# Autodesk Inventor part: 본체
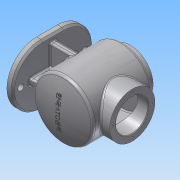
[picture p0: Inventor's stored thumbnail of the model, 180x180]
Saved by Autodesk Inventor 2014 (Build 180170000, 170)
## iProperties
Created: 2016-04
Part Number: 본체
Material: 알루미늄 6061
Document SubType Name: Modeling
Designer: 601-
Density: 2.71 g/cm^3
Appearance: 알루미늄 - 평지
Mass: 1195.29 g
Surface Area: 1196.97 cm^2
Volume: 441.067 cm^3
Author: 601-
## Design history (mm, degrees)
sketch "스케치2"
  geometry: L1 (-17.5, 0)-(17.5, 0); L2 (-17.5, -50)-(17.5, -50); L3 (17.5, 50)-(-17.5, 50); L4 (-67.5, 0)-(67.5, 0); L5 (0, 50)-(0, -50); A1 r 50 centre (-17.5, 0) between (-17.5, 50) and (-17.5, -50); A2 r 50 centre (17.5, 0) between (17.5, -50) and (17.5, 50); 1 further point
  constraints: 12 end point, 6 point on circle, 4 tangent, 3 midpoint, 2 centre point, 1 horizontal, 1 parallel
  dimensions: "d0" = 135 distance of L4.end L4.start; "d1" = 100 distance of L5.end L5.start
extrude "돌출1" new body sketch "스케치2" distance "d2" = 10; taper "d3" = 0 deg
sketch "스케치3"
  geometry: L1 (0, -67.5)-(0, 67.5); C1 r 5 at (0, -54); C2 r 5 at (0, 54); A1 r 50 centre (0, 17.5) between (50, 17.5) and (-50, 17.5) reference; A2 r 50 centre (0, -17.5) between (-50, -17.5) and (50, -17.5) reference; 1 further point
  constraints: 2 centre point, 2 end point, 2 point on circle, 2 point on line, 1 equal radius
  dimensions: "d4" = 10 diameter of C1; "d5" = 108 distance of C2.centre C1.centre; "d6" = 54 distance of point (0, 0) C1.centre
extrude "돌출2" cut sketch "스케치3" stored distance "d7" = 10; taper "d8" = 0 deg
sketch "스케치5"
  geometry: L1 (0, 0)-(79, 0); L2 (0, -17.5)-(0, 17.5) reference; L3 (79, 61)-(79, -61); L4 (79, 61)-(117, 61); L5 (117, 61)-(117, 49); L6 (117, 49)-(79, 49); L7 (79, 49)-(79, 61); L8 (79, 49)-(129, 49); L9 (129, 49)-(129, -51); L10 (79, -49)-(79, 49); L11 (79, -49)-(79, -61); L12 (79, -49)-(79, -61); L13 (79, -51)-(79, -61); L14 (79, -51)-(129, -51); L15 (79, 49)-(129, 49); L16 (129, 49)-(129, -51); L17 (129, -51)-(79, -51); L18 (79, -51)-(79, 49); L19 (129, -51)-(79, -51); L20 (0, 67.5)-(10, 67.5) reference; L21 (0, -67.5)-(10, -67.5) reference; A1 r 120 centre (81.003, 58.983) between (79, -61) and (129, -51)
  constraints: 36 end point, 6 parallel, 5 perpendicular, 4 collinear, 3 horizontal, 2 midpoint, 2 point on circle, 1 centre point, 1 point on line
  dimensions: "d19" = 79 distance of L1.end L1.start; "d21" = 12 distance of L4.end L5.end; "d22" = 100 diameter of L9 L3; "d23" = 76 diameter of L5 L3; "d25" = 122 distance from line of L12.end L4; "d28" = 120 radius of A1; "d41" = 61 distance from line of L1.end L4
revolve "회전1" stored, may be unused: angle "d29" = 90 deg
revolve "회전2" stored, may be unused: angle "d30" = 90 deg
sketch "스케치8"
  geometry: L1 (-40, 5)-(40, 5); L2 (40, 5)-(40, -5); L3 (40, -5)-(-40, -5); L4 (-40, -5)-(-40, 5); L5 (-40, 5)-(40, -5); L6 (40, 5)-(-40, -5); 1 further point
  constraints: 12 end point, 2 midpoint, 2 parallel, 1 horizontal, 1 perpendicular
  dimensions: "d37" = 80 distance of L1.start L1.end; "d38" = 10 distance of L1.end L2.end
extrude "돌출4" join sketch "스케치8" stored distance "d39" = 10; taper "d40" = 0 deg
sketch "스케치9"
  geometry: L1 (10, 67.5)-(10, 59) reference; L2 (10, 59)-(0, 59) reference; L3 (0, 59)-(0, 67.5) reference; L4 (0, 67.5)-(10, 67.5) reference; L5 (10, -67.5)-(0, -67.5) reference; L6 (0, -67.5)-(0, -59) reference; L7 (0, -59)-(10, -59) reference; L8 (10, -59)-(10, -67.5) reference; L9 (41, 61)-(117, 61) reference; L10 (117, 61)-(117, 49) reference; L11 (117, 49)-(129, 49) reference; L12 (129, 49)-(129, -51) reference; L13 (29, -51)-(29, -5) reference; L14 (10, -5)-(10, -49) reference; L15 (10, -49)-(0, -49) reference; L16 (0, -49)-(0, 49) reference; L17 (0, 49)-(10, 49) reference; L18 (10, 49)-(10, 5) reference; L19 (29, 5)-(29, 49) reference; L20 (29, 49)-(41, 49) reference; L21 (41, 49)-(41, 61) reference; L22 (41, 61)-(117, 61) reference; L23 (79, 46)-(79, -58); L24 (32, -49.018)-(32, 46); L25 (32, 46)-(79, 46); L26 (29, -5)-(10, -5) reference; L27 (10, 5)-(29, 5) reference; A1 r 120 centre (81.003, 58.983) between (79, -61) and (129, -51) reference; A2 r 120 centre (76.997, 58.983) between (29, -51) and (79, -61) reference; A3 r 117 centre (76.997, 58.983) between (32, -49.018) and (79, -58); 1 further point
  constraints: 6 end point, 2 point on circle, 2 symmetric about line, 1 centre point, 1 perpendicular
  dimensions: "d132" = 3 distance between parallel lines of L13 L24
revolve "회전3" sketch "스케치9" stored, may be unused: angle "d46" = 90 deg
sketch "스케치10"
  geometry: C1 r 38 at (0, 0) reference; C2 r 27 at (0, 0); 1 further point
  constraints: 1 centre point, 1 coincident
  dimensions: "d47" = 54 diameter of C2
extrude "돌출5" cut sketch "스케치10" distance "d48" = 15; taper "d49" = 0 deg
sketch "스케치11" dims "d50" = 65
  geometry: C1 r 38 at (0, 0) reference; 3 further points
  constraints: 1 coincident, 1 horizontal alignment, 2 other
hole "구멍1" sketch "스케치11" at (32.5, 0) diameter "d51" = 3.242; stored, may be unused: countersink angle "d55" = 90 deg, drill point angle "d57" = 118 deg; dims "d52" = 8, "d53" = 4, "d54" = 2, "d56" = 10
node "작업 평면2"
sketch "스케치12"
  geometry: L1 (49, 50)-(49, -50) reference; C1 r 38 at (-1, 0); 1 further point
  constraints: 1 centre point
  dimensions: "d102" = 50 distance from line of L1 C1.centre; "d103" = 76 diameter of C1
extrude "돌출6" join sketch "스케치12" stored distance "d63" = 10; taper "d64" = 0 deg
chamfer "모따기1" distance "d89" = 3; stored, may be unused: second distance "d90" = 2, angle "d91" = 45 deg
fillet "모깎기4" dims "d92" = 3
fillet "모깎기6" dims "d94" = 5, "d95" = 2
chamfer "모따기2" distance "d96" = 1; stored, may be unused: second distance "d97" = 2, angle "d98" = 45 deg
sketch "스케치16"
  geometry: L1 (107, 61)-(51, 61) reference; L2 (79, 61)-(79, -71.856); 1 further point
  constraints: 2 end point, 1 midpoint, 1 perpendicular
fillet "모깎기7" dims "d101" = 3
sketch "스케치18"
  geometry: C1 r 38 at (0, 0) reference; C2 r 27 at (0, 0); 1 further point
  constraints: 1 centre point, 1 coincident
  dimensions: "d104" = 54 diameter of C2
extrude "돌출8" cut sketch "스케치18" stored distance "d105" = 10; taper "d106" = 0 deg
sketch "스케치19" dims "d107" = 65
  geometry: C1 r 38 at (0, 0) reference; 3 further points
  constraints: 1 coincident, 1 vertical alignment, 2 other
hole "구멍4" sketch "스케치19" at (0, 32.5) diameter "d108" = 3.242; stored, may be unused: countersink angle "d112" = 90 deg, drill point angle "d114" = 118 deg; dims "d109" = 8, "d110" = 4, "d111" = 2, "d113" = 10
fillet "모깎기8" dims "d118" = 3
chamfer "모따기3" distance "d119" = 1; stored, may be unused: second distance "d120" = 2, angle "d121" = 45 deg
sketch "스케치20"
  geometry: L1 (52, 60)-(106, 60) reference; L2 (79, 60)-(79, -71.197); 1 further point
  constraints: 2 end point, 1 midpoint, 1 perpendicular
node "작업 평면5"
sketch "스케치21"
  geometry: C1 r 50 at (0, 0) reference; 2 further points
  constraints: 1 coincident, 1 other
feature "엠보싱2" sketch "스케치21" dims "d0" = 135, "d1" = 100, "d7" = 10, "d8" = 0, "d122" = 0.5, "d123" = 0
sketch "스케치22"
  geometry: L1 (10, 64.5)-(10, 17.5) reference; L2 (10, -17.5)-(10, -64.5) reference; L3 (10, 40)-(33.936, 35.779); L4 (33.936, 35.779)-(33.936, -35.779); L5 (33.936, -35.779)-(10, -40); L6 (10, 40)-(10, -40); L7 (0, 0)-(62.313, 0); L8 (49, -2)-(10, -2) reference; 2 further points
  constraints: 10 end point, 2 parallel, 2 point on line, 1 collinear
  dimensions: "d124" = 40 distance from line of L7 L3.start; "d125" = 40 distance from line of L5.end L7; "d126" = 100 deg angle of L1 L3; "d127" = 100 deg angle of L2 L5
extrude "돌출9" join sketch "스케치22" stored distance "d128" = 10; taper "d129" = 0 deg
fillet "모깎기9" dims "d130" = 3
fillet "모깎기10" dims "d131" = 3
node "솔리드1"
pattern_circular "원형 패턴1" dims angle "d59" = 360 deg
pattern_circular "원형 패턴3" dims angle "d116" = 360 deg
node "절단 모서리 투영1"
other parameters: "d61" = 144
